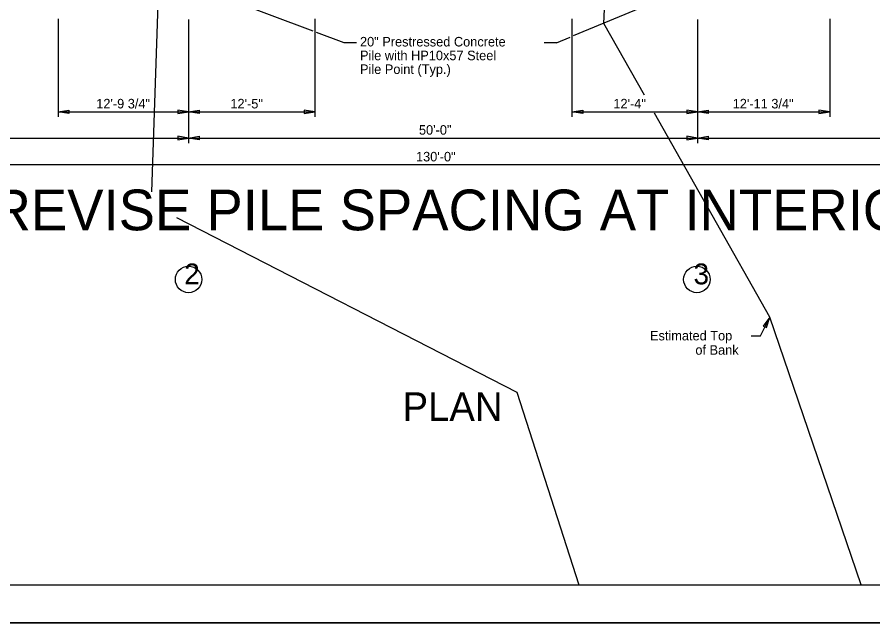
# Model space of a CAD drawing. Extents: x -463 to -191, y 251 to 416.
# Drawn here: x -363.8 to -279.7, y 251.4 to 310.9 of the extents above; entities that cross this region are included whole.
import ezdxf

# ---------------------------------------------------------------- set-up
doc = ezdxf.new("R2010")
doc.units = 0
for name, color, linetype in [('BR_AUTO DIMENSION', 7, 'Continuous'), ('BR_BORDER LINES', 7, 'Continuous'), ('BR_TEXT', 7, 'Continuous'), ('Default', 7, 'Continuous'), ('RD_SHT_IplotShp', 7, 'Continuous')]:
    doc.layers.add(name, color=color, linetype=linetype)

msp = doc.modelspace()

# ---------------------------------------------------------------- linework, layer by layer
at = {"layer": 'BR_AUTO DIMENSION'}
for p, q in [((-334.693, 309.546), (-346.109, 313.838)), ((-309.112, 309.113), (-297.775, 313.838)), ((-359.76, 310.779), (-359.76, 301.134)), ((-346.942, 310.695), (-346.942, 298.555)), ((-334.528, 310.779), (-334.528, 301.134)), ((-309.275, 310.779), (-309.275, 301.134)), ((-296.942, 310.695), (-296.942, 298.555)), ((-283.958, 310.779), (-283.958, 301.134)), ((-331.664, 308.408), (-334.363, 309.422)), ((-310.798, 308.41), (-309.438, 308.977)), ((-330.458, 308.408), (-331.664, 308.408)), ((-310.798, 308.41), (-312.004, 308.41)), ((-359.76, 301.628), (-358.706, 301.804)), ((-359.76, 301.628), (-346.942, 301.628)), ((-358.705, 301.452), (-359.76, 301.628)), ((-358.706, 301.804), (-358.705, 301.452)), ((-346.942, 301.628), (-347.997, 301.804)), ((-347.997, 301.804), (-347.997, 301.452)), ((-347.997, 301.452), (-346.942, 301.628)), ((-346.942, 301.628), (-345.887, 301.804)), ((-345.887, 301.452), (-346.942, 301.628)), ((-346.942, 301.628), (-334.528, 301.628)), ((-345.887, 301.804), (-345.887, 301.452)), ((-334.528, 301.628), (-335.583, 301.804)), ((-335.583, 301.804), (-335.583, 301.452)), ((-335.583, 301.452), (-334.528, 301.628)), ((-309.275, 301.628), (-308.22, 301.804)), ((-308.22, 301.452), (-309.275, 301.628)), ((-309.275, 301.628), (-296.942, 301.628)), ((-308.22, 301.804), (-308.22, 301.452)), ((-296.942, 301.628), (-297.997, 301.804)), ((-297.997, 301.804), (-297.997, 301.452)), ((-297.997, 301.452), (-296.942, 301.628)), ((-296.942, 301.628), (-295.887, 301.804)), ((-295.887, 301.452), (-296.942, 301.628)), ((-296.942, 301.628), (-283.958, 301.628)), ((-295.887, 301.804), (-295.887, 301.452)), ((-285.013, 301.804), (-285.014, 301.452)), ((-285.014, 301.452), (-283.958, 301.628)), ((-283.958, 301.628), (-285.013, 301.804)), ((-386.942, 299.049), (-256.942, 299.049)), ((-346.942, 299.049), (-347.997, 299.225)), ((-347.997, 299.225), (-347.997, 298.873)), ((-347.997, 298.873), (-346.942, 299.049)), ((-346.942, 299.049), (-345.887, 299.225)), ((-345.887, 298.873), (-346.942, 299.049)), ((-345.887, 299.225), (-345.887, 298.873)), ((-296.942, 299.049), (-297.997, 299.225)), ((-297.997, 299.225), (-297.997, 298.873)), ((-297.997, 298.873), (-296.942, 299.049)), ((-296.942, 299.049), (-295.887, 299.225)), ((-295.887, 298.873), (-296.942, 299.049)), ((-295.887, 299.225), (-295.887, 298.873)), ((-386.942, 296.469), (-256.942, 296.469)), ((-290.761, 279.642), (-289.85, 281.46)), ((-289.85, 281.46), (-290.48, 280.595)), ((-290.165, 280.438), (-289.85, 281.46)), ((-290.48, 280.595), (-290.165, 280.438)), ((-291.671, 279.642), (-290.761, 279.642)), ((-291.671, 279.642), (-290.761, 279.642))]:
    msp.add_line(p, q, dxfattribs=at)
for centre in [(-346.942, 285.17), (-346.942, 285.17), (-297.006, 285.17)]:
    msp.add_circle(centre, 1.3, dxfattribs=at)
at = {"layer": 'BR_BORDER LINES'}
for p, q in [((-449.129, 255.187), (-196.63, 255.187)), ((-462.879, 251.448), (-192.879, 251.448))]:
    msp.add_line(p, q, dxfattribs=at)
at = {"layer": 'Default'}
for points in [[(-350.569, 293.783), (-348.075, 367.639), (-357.521, 375.932), (-398.853, 389.643)], [(-302.159, 303.26), (-306.131, 310.294), (-303.836, 360.025)], [(-280.868, 255.187), (-289.85, 281.46), (-301.168, 301.505)], [(-348.137, 291.257), (-314.692, 274.095), (-308.593, 255.187)]]:
    msp.add_lwpolyline(points, dxfattribs=at)
at = {"layer": 'RD_SHT_IplotShp'}
msp.add_lwpolyline([(-462.879, 416.438), (-192.879, 416.438), (-192.879, 251.438), (-462.879, 251.438)], close=True, dxfattribs=at)

# ---------------------------------------------------------------- texts
at = {"layer": 'BR_TEXT'}
for s, height, p in [('20" Prestressed Concrete', 0.9375, (-330.101, 308.051)), ('Pile with HP10x57 Steel ', 0.9375, (-330.101, 306.7)), ('Pile Point (Typ.)', 0.9375, (-330.101, 305.349)), ('12\'-9 3/4"', 0.9375, (-356.014, 301.965)), ('12\'-5"', 0.9375, (-342.837, 301.965)), ('12\'-4"', 0.9375, (-305.211, 301.965)), ('12\'-11 3/4"', 0.9375, (-293.486, 301.965)), ('50\'-0"', 0.9375, (-324.31, 299.386)), ('130\'-0"', 0.9375, (-324.6, 296.761)), ('REVISE PILE SPACING AT INTERIOR BENTS', 4, (-366.294, 289.994)), ('2', 2.045, (-347.366, 284.69)), ('3', 2.045, (-297.334, 284.69)), ('Estimated Top', 0.9375, (-301.612, 279.183)), ('of Bank', 0.9375, (-297.153, 277.776)), ('PLAN', 2.8125, (-325.924, 271.27))]:
    msp.add_text(s, height=height, dxfattribs=at).set_placement(p)

doc.saveas('drawing.dxf')
